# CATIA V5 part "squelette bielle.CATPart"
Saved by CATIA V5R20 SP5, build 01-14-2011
Part number: squelette bielle
Publications: "L_bielle", "Point.8", "Abis", "Droite.4", "Droite.5", "Point.27"
Bounding box of the stored display mesh (mm): x -1453 to 10078, y 280 to 402.431, z 550 to 882.553
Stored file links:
  F:\iao fini\squelette bielle.CATPart
  F:\iao fini\iao-finipbgliss.CATProduct
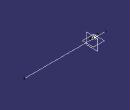
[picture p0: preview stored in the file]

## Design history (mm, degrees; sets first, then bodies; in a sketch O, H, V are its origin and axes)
Parameters
  L_bielle = 350 mm
Point1 "A": linked copy from another document
Line1: linked copy from another document
Set1
  Plane1 "Plancouli": linked copy from another document
Body1 (main body)
  Set2
    Plane2 "Planbielle": type Offset, RefPlane yz-plane, Offset 200
    Point2 "Abis": type OnPlane, Support Plane2, H 280, V 550, Direction (0, 1, 0)
    Point3 "B": type OnPlane, Support Plane2, H 402.431, V 882.553, Direction (0, 1, 0)
    Line2: type PtPt, FirstPoint Point2, SecondPoint Point3, Support Plane2, Start 531, End 390
    Line3: type PtDir, RefPoint Point2, Direction Line2, Support Plane2, Start 0, End -350 {= -L_bielle}
    Point4: type OnCurve, Support Line3, Ratio 0
    Line4: type Normal, RefPoint Point4, RefSkin Plane2, Start 364, End -584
